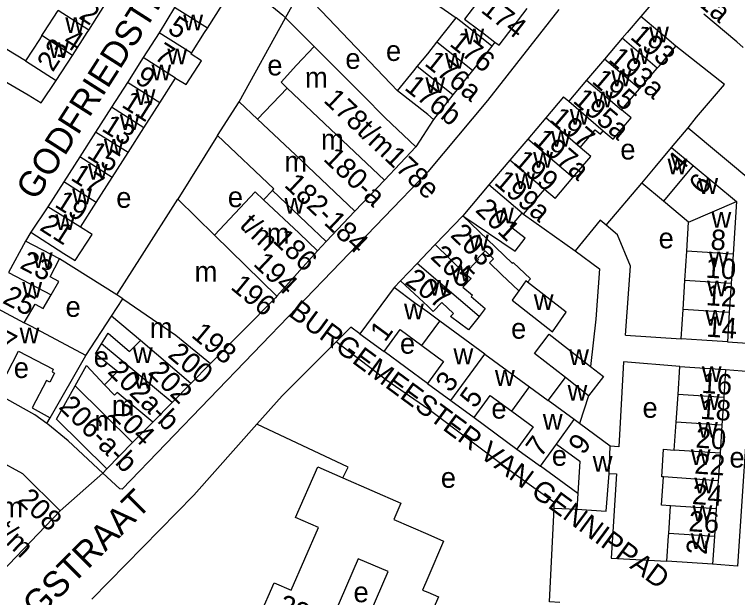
# Model space of a CAD drawing. Extents: x 159700 to 161346, y 381730 to 382922.
# Drawn here: x 160419.3 to 160560.5, y 382139.7 to 382253.5 of the extents above; entities that cross this region are included whole.
import ezdxf

# ---------------------------------------------------------------- set-up
doc = ezdxf.new("R2010")
doc.units = 0
for name, color, linetype in [('BLT_Basislijn', 7, 'Continuous'), ('BLT_Bebouwing', 7, 'Continuous'), ('BLT_Centroide', 7, 'Continuous'), ('BLT_Huisnummer', 7, 'Continuous'), ('BLT_Huisnummer_ tussenligend', 7, 'Continuous'), ('BLT_Huisnummer_reeks', 7, 'Continuous'), ('BLT_Onderdoorgang_en_onderverdeling', 7, 'Continuous'), ('BLT_Onderverdeling_panden', 7, 'Continuous'), ('BLT_Straatnaam', 7, 'Continuous'), ('BLT_Straatnaam_verkleind', 7, 'Continuous'), ('BLT_Vlakafsluiter', 7, 'Continuous')]:
    doc.layers.add(name, color=color, linetype=linetype)

msp = doc.modelspace()

# ---------------------------------------------------------------- linework, layer by layer
at = {"layer": 'BLT_Basislijn'}
for p, q in [((160546.97, 382259.42), (160541.61, 382253.18)), ((160472.23, 382252.88), (160475.22, 382258.29)), ((160477.91, 382255.64), (160494.11, 382238.66)), ((160463.17, 382236.48), (160472.23, 382252.88)), ((160472.23, 382252.88), (160477.82, 382247.31)), ((160560.37, 382248.17), (160553.9, 382253.59)), ((160421.46, 382244.49), (160409.7, 382251.58)), ((160513.13, 382248.13), (160512.53, 382247.34)), ((160561.62, 382247.12), (160560.37, 382248.17)), ((160501.15, 382233.06), (160497.68, 382227.68)), ((160547.63, 382227.58), (160550.83, 382231.42)), ((160550.83, 382231.42), (160565.44, 382219.21)), ((160458.94, 382229.91), (160451.23, 382217.44)), ((160534.87, 382212.38), (160541.82, 382220.61)), ((160422.48, 382211.02), (160421.43, 382209.28)), ((160439.29, 382198.8), (160428.1, 382205.79)), ((160494.68, 382201.53), (160493.42, 382200.21)), ((160433.24, 382186.94), (160438.28, 382194.6)), ((160538.6, 382190.92), (160549.5, 382190.2)), ((160558.54, 382189.63), (160563.42, 382189.3)), ((160499.96, 382181.48), (160491.5, 382187.72)), ((160549.24, 382184.76), (160538.25, 382185.7)), ((160558.16, 382184.17), (160563.06, 382183.84)), ((160563.06, 382183.84), (160560.5, 382145.81)), ((160425.6, 382173.68), (160426.25, 382174.79)), ((160509.07, 382174.8), (160517.39, 382168.64)), ((160529.31, 382159.96), (160522.02, 382165.33)), ((160437.36, 382164.83), (160436.55, 382163.94)), ((160524.67, 382157.12), (160529.12, 382156.89)), ((160560.5, 382145.81), (160555.63, 382146.15))]:
    msp.add_line(p, q, dxfattribs=at)
for points in [[(160356.86, 382275.86), (160422, 382237.88), (160424.55, 382236.26), (160427.43, 382240.63)], [(160480.57, 382267.14), (160492.87, 382260.8), (160500, 382256.78), (160505.58, 382252.87)], [(160462.71, 382260.83), (160471.68, 382253.43), (160472.23, 382252.88)], [(160525.61, 382254.52), (160511.7, 382236.76), (160500, 382222.84), (160440.36, 382160.85), (160439.9, 382160.89), (160436.55, 382163.94)], [(160550.83, 382231.42), (160552.52, 382233.46), (160557.96, 382239.88), (160548.47, 382247.35)], [(160518.7, 382214.54), (160528.77, 382207.38)], [(160534.87, 382212.38), (160533.66, 382213.36), (160528.77, 382207.38)], [(160538.6, 382190.92), (160539.61, 382204.41), (160537.04, 382210.52), (160534.87, 382212.38)], [(160528.77, 382207.38), (160533.58, 382203.88), (160532.83, 382194.03), (160531.78, 382184.79)], [(160486.78, 382191.18), (160484.99, 382192.49), (160482.15, 382189.62)], [(160482.15, 382189.62), (160471.59, 382179.07), (160466.64, 382173.49)], [(160524.67, 382157.12), (160524.69, 382157.66), (160524.64, 382158.28), (160516.8, 382163.86), (160500, 382176.52), (160491.99, 382182.07), (160482.15, 382189.62)], [(160425.6, 382173.68), (160423.28, 382175.35), (160412.31, 382181.48), (160409.07, 382184.62), (160409.84, 382187.53)], [(160538.25, 382185.7), (160537.31, 382169.11), (160535.66, 382169.22)], [(160436.55, 382163.94), (160429.8, 382170.27), (160425.82, 382173.53), (160425.6, 382173.68)], [(160466.64, 382173.49), (160454.36, 382159.67), (160434.39, 382139.32)], [(160483.46, 382163.05), (160484.48, 382165.11), (160466.64, 382173.49)], [(160535.43, 382163.88), (160536.86, 382163.79), (160535.81, 382147.37), (160546.71, 382146.74)], [(160525.78, 382138.71), (160523.76, 382138.82), (160524.67, 382157.12)]]:
    msp.add_lwpolyline(points, dxfattribs=at)
at = {"layer": 'BLT_Bebouwing'}
for p, q in [((160433.8, 382250.49), (160436.98, 382255.43)), ((160450.58, 382254.88), (160447.54, 382249.99)), ((160447.54, 382249.99), (160444.44, 382245.13)), ((160537.99, 382248.91), (160534.5, 382244.8)), ((160487.31, 382237.77), (160477.82, 382247.31)), ((160512.53, 382247.34), (160508.73, 382242.58)), ((160421.46, 382244.49), (160427.43, 382240.63)), ((160427.43, 382240.63), (160430.62, 382245.56)), ((160444.44, 382245.13), (160441.35, 382240.28)), ((160534.5, 382244.8), (160531.03, 382240.72)), ((160541.35, 382239.03), (160544.81, 382243.04)), ((160508.73, 382242.58), (160504.94, 382237.82)), ((160441.35, 382240.28), (160438.25, 382235.42)), ((160447.68, 382236.27), (160450.78, 382241.12)), ((160466.79, 382233.11), (160472.53, 382239.18)), ((160537.83, 382234.95), (160541.35, 382239.03)), ((160504.94, 382237.82), (160501.15, 382233.06)), ((160526.54, 382237.44), (160523.06, 382233.36)), ((160526.54, 382237.44), (160527.53, 382236.59)), ((160444.58, 382231.41), (160447.68, 382236.27)), ((160458.94, 382229.91), (160463.17, 382236.48)), ((160463.17, 382236.48), (160466.79, 382233.11)), ((160438.25, 382235.42), (160435.15, 382230.57)), ((160523.06, 382233.36), (160519.54, 382229.22)), ((160435.15, 382230.57), (160432.05, 382225.71)), ((160441.48, 382226.56), (160444.58, 382231.41)), ((160529.78, 382227.58), (160532.71, 382231.03)), ((160519.54, 382229.22), (160516.04, 382225.11)), ((160491.54, 382221.19), (160497.68, 382227.68)), ((160531.88, 382225.8), (160529.78, 382227.58)), ((160547.63, 382227.58), (160551.85, 382224.05)), ((160438.39, 382221.7), (160441.48, 382226.56)), ((160432.05, 382225.71), (160428.95, 382220.86)), ((160516.04, 382225.11), (160511.95, 382220.26)), ((160528.37, 382221.68), (160531.88, 382225.8)), ((160428.95, 382220.86), (160425.85, 382216)), ((160435.29, 382216.85), (160438.39, 382221.7)), ((160485.79, 382215.12), (160491.54, 382221.19)), ((160524.89, 382217.59), (160528.37, 382221.68)), ((160546.03, 382217.09), (160541.82, 382220.61)), ((160469.68, 382219.17), (160467.96, 382217.35)), ((160511.95, 382220.26), (160506.83, 382214.24)), ((160518.7, 382214.54), (160522.81, 382219.37)), ((160524.89, 382217.59), (160522.81, 382219.37)), ((160432.19, 382211.99), (160435.29, 382216.85)), ((160451.23, 382217.44), (160458.36, 382210.46)), ((160550.94, 382212.98), (160546.03, 382217.09)), ((160425.85, 382216), (160422.48, 382211.02)), ((160480.2, 382209.21), (160485.79, 382215.12)), ((160518.47, 382214.73), (160518.7, 382214.54)), ((160501.46, 382208.62), (160506.83, 382214.24)), ((160550.58, 382207.29), (160550.94, 382212.98)), ((160421.43, 382209.28), (160418.15, 382203.12)), ((160480.2, 382209.21), (160478.51, 382207.36)), ((160478.51, 382207.36), (160470.55, 382198.51)), ((160550.22, 382201.59), (160550.58, 382207.29)), ((160559.62, 382206.71), (160559.26, 382201.02)), ((160497.92, 382204.92), (160494.68, 382201.53)), ((160549.86, 382195.9), (160550.22, 382201.59)), ((160559.26, 382201.02), (160558.9, 382195.32)), ((160438.28, 382194.6), (160440.49, 382198.03)), ((160440.49, 382198.03), (160439.29, 382198.8)), ((160549.5, 382190.2), (160549.86, 382195.9)), ((160558.9, 382195.32), (160558.54, 382189.63)), ((160443.94, 382189.86), (160438.28, 382194.6)), ((160486.78, 382191.18), (160491.5, 382187.72)), ((160426.25, 382174.79), (160433.24, 382186.94)), ((160511.18, 382187.18), (160519.89, 382180.79)), ((160457.58, 382185.35), (160453.73, 382181.44)), ((160548.88, 382179.33), (160549.24, 382184.76)), ((160558.16, 382184.17), (160557.8, 382178.74)), ((160453.73, 382181.44), (160450.12, 382177.78)), ((160499.96, 382181.48), (160504.54, 382178.12)), ((160504.54, 382178.12), (160509.07, 382174.8)), ((160531.4, 382179.03), (160529.61, 382173.66)), ((160548.52, 382173.9), (160548.88, 382179.33)), ((160557.8, 382178.74), (160557.44, 382173.31)), ((160450.12, 382177.78), (160446.32, 382173.92)), ((160446.32, 382173.92), (160442.37, 382169.91)), ((160548.16, 382168.47), (160548.52, 382173.9)), ((160535.65, 382169.23), (160529.61, 382173.66)), ((160557.44, 382173.31), (160557.08, 382167.87)), ((160522.02, 382165.33), (160525.16, 382169.62)), ((160517.39, 382168.64), (160522.02, 382165.33)), ((160557.08, 382167.87), (160556.71, 382162.44)), ((160556.71, 382162.44), (160556.35, 382157.01)), ((160529.31, 382159.96), (160529.12, 382156.89)), ((160547.07, 382152.17), (160547.43, 382157.6)), ((160556.35, 382157.01), (160555.99, 382151.58)), ((160555.99, 382151.58), (160555.63, 382146.15)), ((160555.63, 382146.15), (160546.71, 382146.74))]:
    msp.add_line(p, q, dxfattribs=at)
for points in [[(160506.01, 382268.51), (160501.77, 382262.27), (160510.17, 382256.59), (160507.17, 382252.65), (160509.96, 382250.54), (160510.67, 382250), (160513.13, 382248.13)], [(160456.97, 382250.84), (160459.91, 382255.49), (160459.51, 382255.76), (160459.64, 382255.97)], [(160424.65, 382249.41), (160425.04, 382250), (160427.84, 382254.34)], [(160513.13, 382248.13), (160513.94, 382247.52), (160515.83, 382250), (160519.41, 382254.71)], [(160501.79, 382248.12), (160503.29, 382250), (160505.58, 382252.87)], [(160512.53, 382247.34), (160509.19, 382250.01), (160508.73, 382250.36), (160508.62, 382250.45), (160505.58, 382252.87)], [(160541.61, 382253.18), (160538.92, 382250), (160537.99, 382248.91)], [(160548.47, 382247.35), (160545.36, 382250), (160541.61, 382253.18)], [(160430.62, 382245.56), (160433.48, 382250), (160433.8, 382250.49)], [(160453.88, 382245.98), (160456.44, 382250), (160456.97, 382250.84)], [(160424.65, 382249.41), (160424.18, 382248.68), (160421.46, 382244.49)], [(160472.53, 382239.18), (160471.37, 382240.3), (160474.4, 382243.67), (160477.82, 382247.31)], [(160497.97, 382243.38), (160500, 382245.87), (160501.79, 382248.12)], [(160544.81, 382243.04), (160545.24, 382243.54), (160548.47, 382247.35)], [(160450.78, 382241.12), (160452.83, 382239.84), (160455.81, 382244.5), (160453.78, 382245.79), (160453.88, 382245.98)], [(160494.11, 382238.66), (160497.27, 382242.53), (160497.97, 382243.38)], [(160531.03, 382240.72), (160527.53, 382236.59)], [(160497.68, 382227.68), (160491.71, 382233.35), (160487.31, 382237.77)], [(160501.15, 382233.06), (160500, 382233.98), (160494.11, 382238.66)], [(160534.28, 382230.83), (160536.21, 382229.18), (160539.73, 382233.33), (160537.83, 382234.95)], [(160532.71, 382231.03), (160533.72, 382230.18), (160534.28, 382230.83)], [(160469.68, 382219.17), (160469.96, 382219.46), (160458.94, 382229.91)], [(160541.82, 382220.61), (160544.42, 382223.74), (160547.63, 382227.58)], [(160551.85, 382224.05), (160560.28, 382217.01)], [(160458.36, 382210.46), (160466.34, 382218.88), (160467.96, 382217.35)], [(160439.29, 382198.8), (160444.23, 382206.51), (160451.23, 382217.44)], [(160560.28, 382217.01), (160559.62, 382206.71)], [(160516.18, 382212.07), (160518.01, 382214.2), (160518.47, 382214.73)], [(160506.83, 382214.24), (160516.52, 382204.96), (160516.67, 382205.11), (160520.08, 382201.88), (160519.49, 382201.27)], [(160506.83, 382214.24), (160517.08, 382207.29), (160519.03, 382209.83), (160516.18, 382212.07)], [(160422.48, 382211.02), (160428.98, 382206.87), (160431.19, 382205.46), (160434.46, 382210.59), (160432.19, 382211.99)], [(160428.1, 382205.79), (160421.43, 382209.28)], [(160501.46, 382208.62), (160500, 382207.09), (160497.92, 382204.92)], [(160517.77, 382199.57), (160514.43, 382202.78), (160512.07, 382205.04), (160512.83, 382205.83), (160511.2, 382207.39), (160509.73, 382205.86), (160509.9, 382205.7), (160507.28, 382202.97)], [(160426.47, 382198.76), (160427.97, 382201.38), (160426.26, 382202.28), (160428.1, 382205.79)], [(160507.28, 382202.97), (160508.49, 382201.95), (160506.88, 382200.27), (160508.73, 382198.69), (160508.52, 382198.47), (160511.25, 382196.14), (160510.03, 382194.57)], [(160494.68, 382201.53), (160498.33, 382198.12), (160500, 382196.55), (160501.08, 382195.54), (160502.79, 382197.29), (160505.05, 382195.13)], [(160517.77, 382199.57), (160516.47, 382197.73), (160524.38, 382191.58), (160527.06, 382195.4), (160519.49, 382201.27)], [(160493.42, 382200.21), (160486.78, 382191.18)], [(160502.38, 382193.63), (160500, 382195.38), (160497.45, 382197.25), (160493.42, 382200.21)], [(160421.22, 382193.29), (160423.33, 382196.93), (160424.93, 382196.09), (160426.47, 382198.76)], [(160470.55, 382198.51), (160470.31, 382198.23), (160457.58, 382185.35)], [(160510.03, 382194.57), (160507.99, 382191.95), (160504.48, 382194.54), (160505.05, 382195.13)], [(160511.18, 382187.18), (160502.38, 382193.64)], [(160433.24, 382186.94), (160422.61, 382192.57), (160421.22, 382193.29)], [(160436.33, 382189.23), (160437.6, 382191.32), (160441.79, 382187.74), (160443.94, 382189.86)], [(160491.5, 382187.72), (160494.62, 382191.98), (160498.87, 382188.86)], [(160526.93, 382182.62), (160520.85, 382187.34), (160523.75, 382191.07), (160531.78, 382184.79)], [(160558.54, 382189.63), (160553.55, 382189.95), (160549.5, 382190.2)], [(160436.89, 382181.22), (160439.42, 382183.78), (160439.49, 382183.72), (160435.14, 382187.26), (160436.33, 382189.23)], [(160498.87, 382188.86), (160503.1, 382185.76), (160499.96, 382181.48)], [(160409.84, 382187.53), (160417.79, 382183.36), (160420.11, 382187.79), (160426.89, 382184.26)], [(160426.89, 382184.26), (160426.64, 382183.76), (160427.14, 382183.5), (160426.21, 382181.71), (160425.56, 382182.06), (160422.79, 382176.74), (160426.25, 382174.79)], [(160431.15, 382181.02), (160433.35, 382184.95), (160436.89, 382181.22)], [(160531.78, 382184.79), (160534.32, 382182.8), (160531.4, 382179.03)], [(160549.24, 382184.76), (160553.17, 382184.5), (160558.16, 382184.17)], [(160523.51, 382178.14), (160526.93, 382182.62)], [(160437.36, 382164.83), (160427.52, 382174.52), (160431.15, 382181.02)], [(160519.89, 382180.79), (160523.51, 382178.14)], [(160509.07, 382174.8), (160512.23, 382179.09), (160516.4, 382176.03)], [(160516.4, 382176.03), (160520.57, 382172.97), (160517.39, 382168.64)], [(160442.37, 382169.91), (160437.36, 382164.83)], [(160525.16, 382169.62), (160529.7, 382166.29), (160529.31, 382159.96)], [(160535.43, 382163.88), (160535.65, 382169.23)], [(160546.05, 382163.22), (160545.7, 382163.24), (160546.05, 382168.62), (160548.16, 382168.47)], [(160416.04, 382166.47), (160420.87, 382163.86), (160428.26, 382156.58)], [(160460.12, 382123.53), (160465.9, 382136.74), (160467.2, 382136.17), (160469.99, 382142.55), (160473.32, 382141.09), (160478.68, 382153.35), (160474.2, 382155.31), (160478.52, 382165.2), (160483.46, 382163.05)], [(160483.46, 382163.05), (160494.77, 382158.11), (160493.37, 382154.91), (160500, 382152.01), (160503.08, 382150.67), (160500, 382143.48), (160498.97, 382141.13), (160500.01, 382140.68), (160502.1, 382139.78), (160500, 382134.95)], [(160529.12, 382156.89), (160534.87, 382156.52), (160535.43, 382163.88)], [(160547.43, 382157.6), (160545.68, 382157.72), (160546.05, 382163.22)], [(160428.26, 382156.58), (160413.85, 382141.6)], [(160546.71, 382146.74), (160547.04, 382151.73), (160547.07, 382152.17)]]:
    msp.add_lwpolyline(points, dxfattribs=at)
msp.add_lwpolyline([(160486.45, 382147.24), (160481.7, 382136.23), (160487.52, 382133.72), (160492.27, 382144.73)], close=True, dxfattribs=at)
at = {"layer": 'BLT_Onderdoorgang_en_onderverdeling'}
for points in [[(160480.2, 382209.21), (160476.35, 382212.86), (160469.68, 382219.17)], [(160467.96, 382217.35), (160474.88, 382210.8), (160478.51, 382207.36)]]:
    msp.add_lwpolyline(points, dxfattribs=at)
at = {"layer": 'BLT_Onderverdeling_panden'}
for p, q in [((160433.8, 382250.49), (160427.84, 382254.34)), ((160456.97, 382250.84), (160450.58, 382254.88)), ((160430.62, 382245.56), (160424.65, 382249.41)), ((160453.88, 382245.98), (160447.54, 382249.99)), ((160544.81, 382243.04), (160537.99, 382248.91)), ((160508.73, 382242.58), (160501.79, 382248.12)), ((160450.78, 382241.12), (160444.44, 382245.13)), ((160541.35, 382239.03), (160534.5, 382244.8)), ((160504.94, 382237.82), (160497.97, 382243.38)), ((160447.68, 382236.27), (160441.35, 382240.28)), ((160531.03, 382240.72), (160537.83, 382234.95)), ((160472.53, 382239.18), (160481.03, 382231.14)), ((160527.53, 382236.59), (160534.28, 382230.83)), ((160444.58, 382231.41), (160438.25, 382235.42)), ((160466.79, 382233.11), (160475.28, 382225.07)), ((160529.78, 382227.58), (160523.06, 382233.36)), ((160441.48, 382226.56), (160435.15, 382230.57)), ((160481.03, 382231.14), (160491.54, 382221.19)), ((160528.37, 382221.68), (160519.54, 382229.22)), ((160438.39, 382221.7), (160432.05, 382225.71)), ((160475.28, 382225.07), (160485.79, 382215.12)), ((160522.81, 382219.37), (160516.04, 382225.11)), ((160551.85, 382224.05), (160546.03, 382217.09)), ((160435.29, 382216.85), (160428.95, 382220.86)), ((160518.47, 382214.73), (160511.95, 382220.26)), ((160550.94, 382212.98), (160560.28, 382217.01)), ((160432.19, 382211.99), (160425.85, 382216)), ((160458.36, 382210.46), (160470.55, 382198.51)), ((160501.46, 382208.62), (160507.28, 382202.97)), ((160559.62, 382206.71), (160550.58, 382207.29)), ((160510.03, 382194.57), (160497.92, 382204.92)), ((160418.15, 382203.12), (160426.47, 382198.76)), ((160559.26, 382201.02), (160550.22, 382201.59)), ((160414.76, 382196.76), (160421.22, 382193.29)), ((160558.9, 382195.32), (160549.86, 382195.9)), ((160498.87, 382188.86), (160502.38, 382193.64)), ((160453.73, 382181.44), (160443.94, 382189.86)), ((160450.12, 382177.78), (160436.33, 382189.23)), ((160504.54, 382178.12), (160511.18, 382187.18)), ((160531.4, 382179.03), (160526.93, 382182.62)), ((160442.37, 382169.91), (160431.15, 382181.02)), ((160516.4, 382176.03), (160519.89, 382180.79)), ((160528.58, 382174.42), (160523.51, 382178.14)), ((160557.8, 382178.74), (160548.88, 382179.33)), ((160525.16, 382169.62), (160528.58, 382174.42)), ((160529.61, 382173.66), (160528.58, 382174.42)), ((160557.44, 382173.31), (160548.52, 382173.9)), ((160557.08, 382167.87), (160548.16, 382168.47)), ((160556.71, 382162.44), (160546.05, 382163.22)), ((160556.35, 382157.01), (160547.43, 382157.6)), ((160555.99, 382151.58), (160547.07, 382152.17))]:
    msp.add_line(p, q, dxfattribs=at)
for points in [[(160519.49, 382201.27), (160519.15, 382201.54), (160517.77, 382199.57)], [(160440.49, 382198.03), (160450.85, 382190.93), (160457.58, 382185.35)], [(160446.32, 382173.92), (160439.35, 382179.7), (160438.83, 382179.17), (160436.89, 382181.22)]]:
    msp.add_lwpolyline(points, dxfattribs=at)
at = {"layer": 'BLT_Vlakafsluiter'}
msp.add_line((160428.26, 382156.58), (160436.55, 382163.94), dxfattribs=at)

# ---------------------------------------------------------------- texts
at = {"layer": 'BLT_Centroide'}
for s, p in [('w', (160429.23, 382249.94)), ('w', (160452.27, 382250.44)), ('w', (160507.16, 382247.72)), ('w', (160543.24, 382248.12)), ('w', (160426.03, 382245.03)), ('e', (160491.85, 382244.47)), ('w', (160449.16, 382243.8)), ('e', (160483.92, 382242.92)), ('w', (160503.37, 382242.97)), ('w', (160539.55, 382243.84)), ('e', (160468.68, 382241.64)), ('w', (160446.06, 382240.69)), ('m', (160476.03, 382239.26)), ('w', (160535.87, 382239.53)), ('w', (160499.55, 382238.22)), ('w', (160442.96, 382235.84)), ('w', (160532.3, 382235.41)), ('w', (160527.74, 382232.03)), ('w', (160439.87, 382231)), ('m', (160479.16, 382227.16)), ('w', (160524.09, 382227.72)), ('w', (160436.77, 382226.12)), ('e', (160537.61, 382225.22)), ('w', (160520.59, 382223.59)), ('m', (160472.02, 382222.84)), ('w', (160546.83, 382222.33)), ('w', (160433.66, 382221.28)), ('w', (160517.08, 382219.47)), ('w', (160552.84, 382218.5)), ('w', (160430.57, 382216.44)), ('e', (160460.97, 382215.91)), ('e', (160439.18, 382215.79)), ('w', (160472.05, 382214.62)), ('w', (160512.95, 382212.72)), ('w', (160555.41, 382211.88)), ('w', (160427.3, 382211.44)), ('m', (160468.56, 382208.81)), ('w', (160508.06, 382207.44)), ('e', (160545.09, 382207.87)), ('w', (160422.9, 382204.03)), ('w', (160554.91, 382204.16)), ('m', (160454.48, 382201.34)), ('w', (160504.47, 382201.45)), ('w', (160420.84, 382198.22)), ('w', (160500.31, 382198.6)), ('w', (160554.55, 382198.47)), ('w', (160520.71, 382195.84)), ('e', (160429.28, 382194.48)), ('w', (160495.38, 382193.97)), ('w', (160554.2, 382192.75)), ('w', (160420.3, 382189.33)), ('m', (160445.72, 382190.34)), ('e', (160516.28, 382190.22)), ('e', (160494.58, 382187.29)), ('w', (160442.43, 382185.44)), ('w', (160505.03, 382185.23)), ('w', (160527.62, 382185.06)), ('e', (160434.78, 382184.69)), ('e', (160419.17, 382182.54)), ('w', (160513.13, 382181)), ('w', (160553.52, 382181.75)), ('w', (160442.62, 382180.48)), ('w', (160527.31, 382178.12)), ('m', (160438.3, 382175.19)), ('w', (160553.16, 382176.31)), ('e', (160512.43, 382174.61)), ('e', (160541.94, 382174.76)), ('m', (160434.94, 382172.22)), ('w', (160522.48, 382172.42)), ('w', (160552.8, 382170.88)), ('e', (160524.24, 382165.39)), ('w', (160551.38, 382165.53)), ('e', (160558.92, 382165.04)), ('w', (160532.22, 382164.22)), ('e', (160502.56, 382161.09)), ('w', (160552.07, 382160.03)), ('m', (160416.56, 382155.31)), ('w', (160551.71, 382154.59)), ('w', (160551.35, 382149.16)), ('e', (160485.51, 382138.74))]:
    msp.add_text(s, height=4, dxfattribs=at).set_placement(p)
at = {"layer": 'BLT_Huisnummer'}
for s, rotation, p in [('191a', 319.667, (160547.95, 382259.44)), ('2', 327.1808, (160431.69, 382252.9)), ('174', 322.0488, (160510.2, 382254.13)), ('5', 327.6601, (160449, 382250.16)), ('4', 327.1813, (160428.57, 382247.72)), ('193', 319.3225, (160539.36, 382248.94)), ('23', 57.1793, (160426.79, 382242.14)), ('176', 321.4359, (160504.07, 382247.57)), ('176a', 321.4379, (160499.19, 382243.75)), ('193a', 319.3226, (160535.11, 382244.56)), ('9', 327.6601, (160442.63, 382240.4)), ('195', 319.6593, (160531.85, 382240.28)), ('176b', 321.5138, (160495.28, 382238.98)), ('195a', 319.6556, (160528.16, 382236.49)), ('197', 319.6623, (160523.64, 382232.8)), ('13', 327.6601, (160436.13, 382230.95)), ('197a', 319.6593, (160520.33, 382228.6)), ('199', 319.6556, (160516.52, 382224.44)), ('4', 50.1297, (160549.32, 382222.3)), ('17', 327.6577, (160430.08, 382221.35)), ('199a', 319.6515, (160512.78, 382220.49)), ('201', 316.2335, (160509.12, 382215.16)), ('21', 327.4541, (160424.02, 382211.56)), ('203', 316.244, (160504.24, 382210.26)), ('8', 356.3673, (160555.15, 382207.62)), ('205', 316.2297, (160500.35, 382206.03)), ('23', 332.3575, (160420.17, 382204.1)), ('207', 323.7443, (160495.34, 382201.04)), ('12', 356.3673, (160554.24, 382196.77)), ('14', 356.1859, (160554.34, 382190.63)), ('27', 332.3621, (160413.07, 382189.88)), ('1', 53.7374, (160491.66, 382189.4)), ('200', 320.3197, (160449.05, 382186.78)), ('3', 53.7382, (160504.44, 382179.51)), ('16', 356.1906, (160553.38, 382179.64)), ('5', 53.7436, (160509.21, 382176.44)), ('204', 315.4195, (160437.92, 382175.22)), ('20', 356.1898, (160552.22, 382168.96)), ('7', 53.7409, (160522.07, 382166.86)), ('9', 53.7467, (160530.38, 382167.35)), ('26', 356.1898, (160550.85, 382152.63)), ('2', 86.1918, (160554.48, 382147.95))]:
    msp.add_text(s, height=4, rotation=rotation, dxfattribs=at).set_placement(p)
at = {"layer": 'BLT_Huisnummer_ tussenligend'}
for s, rotation, p in [('7', 327.6601, (160446.38, 382244.95)), ('11', 327.6601, (160440.03, 382235.6)), ('15', 327.6601, (160433.26, 382225.73)), ('6', 50.1297, (160553.73, 382218.1)), ('19', 327.6577, (160426.96, 382216.12)), ('10', 356.3673, (160554.17, 382202.15)), ('25', 332.3575, (160416.77, 382197.29)), ('202', 315.4229, (160445.22, 382183.47)), ('18', 356.1906, (160553.16, 382174.56)), ('22', 356.1898, (160552.01, 382163.88)), ('24', 356.1898, (160551.54, 382157.93))]:
    msp.add_text(s, height=4, rotation=rotation, dxfattribs=at).set_placement(p)
at = {"layer": 'BLT_Huisnummer_reeks'}
for s, rotation, p in [('178t/m178e', 316.5718, (160479.49, 382236.59)), ('180-a', 316.5731, (160479.45, 382225.14)), ('182-184', 316.5523, (160471.8, 382220.06)), ('t/m', 316.5718, (160463.08, 382212.14)), ('186', 316.5734, (160469.56, 382209.22)), ('194', 316.5734, (160465.76, 382204.66)), ('196', 320.3197, (160461.32, 382200.07)), ('198', 320.3197, (160453.64, 382190.69)), ('202a-b', 315.4184, (160437.3, 382183.62)), ('206-a-b', 315.4166, (160427.79, 382176.72)), ('208', 316.1952, (160419.73, 382158.54)), ('t/m', 316, (160415.32, 382152.33)), ('229-a', 336.3815, (160470.36, 382136.78))]:
    msp.add_text(s, height=4, rotation=rotation, dxfattribs=at).set_placement(p)
at = {"layer": 'BLT_Straatnaam'}
for s, rotation, p in [('GODFRIEDSTRAAT', 57.4537, (160423.51, 382216.98)), ('HOOGSTRAAT', 45.1327, (160413.2, 382124.53))]:
    msp.add_text(s, height=5, rotation=rotation, dxfattribs=at).set_placement(p)
at = {"layer": 'BLT_Straatnaam_verkleind'}
msp.add_text('BURGEMEESTER VAN GENNIPPAD', height=4, rotation=323.5255, dxfattribs=at).set_placement((160472.61, 382194.83))

doc.saveas('drawing.dxf')
